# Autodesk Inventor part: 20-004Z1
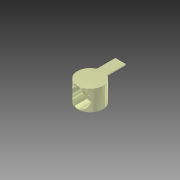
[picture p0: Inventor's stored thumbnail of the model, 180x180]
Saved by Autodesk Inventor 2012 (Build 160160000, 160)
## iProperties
Created: 2004-10
Part Number: 20-004Z1
Material: Zinc ZA-12
Document SubType Name: Modeling
Designer: Autodesk, Inc.
Manufacturer: Standard
Standards Organization: Custom
Description: FASTENER, 40 SERIES, UNIVERSAL
Catalog Web Link: http://www.parker.com/ead/cm1.asp?cmid=809
Vendor: PARKER IPS
Mass: 17.4422 g
Surface Area: 24.0595 cm^2
Volume: 2.88778 cm^3
Density: 6.04 g/cm^3
CAGE: 1LJX3
Dept. ID: Product Design
Description #2: ---
Finish #1: ---
Finish #2: ---
Material ID: ---
Project Number: ---
Author: Autodesk, Inc.
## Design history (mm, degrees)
sketch "Sketch1"
  geometry: C1 r 10 at (0, 0); 1 further point
  constraints: 1 centre point, 1 coincident
  dimensions: "Diameter" = 20 diameter of C1
extrude "Base" new body sketch "Sketch1" taper "d2" = 0 deg; stored distance "Height" = 16
sketch "Sketch3"
  geometry: L1 (-10, -8)-(-10, 8) reference; L2 (10, -8)-(10, 8) reference; L3 (-10, 8)-(10, 8) reference; L4 (10, -8)-(-10, -8) reference; L5 (-10, 2.2)-(0.516, -8); L6 (-0.516, -8)-(10, 2.2); L7 (0, -11.2)-(0, 11.2) reference
  constraints: 4 end point, 4 point on line, 1 other
  dimensions: "d43" = 91.75 deg angle of L6 L5; "d44" = 5.8 distance from line of L3 L5.start
extrude "Pneumatic Cut" cut sketch "Sketch3" stored distance "d45" = 1; taper "d46" = 0 deg
sketch "Sketch2"
  geometry: L1 (-4, 9.165)-(4, 9.165); L2 (4, 9.165)-(4, 23.8); L3 (4, 23.8)-(-4, 23.8); L4 (-4, 23.8)-(-4, 9.165); A1 r 10 centre (0, 0) between (-4, 9.165) and (4, 9.165) reference; 1 further point
  constraints: 8 end point, 2 parallel, 2 point on circle, 1 horizontal, 1 midpoint, 1 perpendicular, 1 vertical alignment
  dimensions: "Tab_Length" = 33.8 dimension on A1 L3; "Tab_Width" = 8 distance of L2.end L3.end
extrude "Tab" join sketch "Sketch2" distance "d13" = 1; taper "d14" = 0 deg
workpoint "Work Point1"
hole "M6 Thru Hole" diameter "d18" = 6.6; stored, may be unused: countersink angle "d22" = 90 deg, drill point angle "d24" = 118 deg; dims "d16" = 10, "d17" = 10, "d19" = 6, "d20" = 10.9, "d21" = 10 (= 0.5 x Diameter), "d23" = 8
hole "M8 Thru Hole" diameter "d5" = 9; stored, may be unused: countersink angle "d9" = 90 deg, drill point angle "d11" = 118 deg; dims "d3" = 10, "d4" = 10, "d6" = 6, "d7" = 15, "d8" = 10 (= 0.5 x Diameter), "d10" = 8
hole "M6 Threaded" diameter "d27" = 4.917; stored, may be unused: countersink angle "d31" = 90 deg, drill point angle "d33" = 118 deg; dims "d25" = 10, "d26" = 10, "d28" = 6, "d29" = 11, "d30" = 6, "d32" = 8
hole "M8 Threaded" diameter "d36" = 6.647; stored, may be unused: countersink angle "d40" = 90 deg, drill point angle "d42" = 118 deg; dims "d34" = 10, "d35" = 10, "d37" = 6, "d38" = 11, "d39" = 6, "d41" = 8
body "Solid1"
other parameters: "d47" = 0, "d48" = 0
